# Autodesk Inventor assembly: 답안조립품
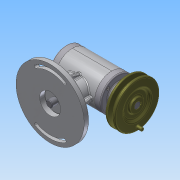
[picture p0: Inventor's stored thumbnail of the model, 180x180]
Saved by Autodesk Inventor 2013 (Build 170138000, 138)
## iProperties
Created: 2017-06
Part Number: 답안조립품
Document SubType Name: Assembly
Designer: Administrator
Mass: 1982.53 g
Surface Area: 1464.34 cm^2
Volume: 498.976 cm^3
Density: 3.97319 g/cm^3
Author: Administrator
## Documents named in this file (15)
- C:\Users\Administrator\Desktop\370608V1013\답안조립품.iam
- C:\Users\Administrator\Desktop\370608V1013\본체.ipt
- C:\Users\Administrator\Desktop\370608V1013\V-벨트풀리.ipt
- C:\Users\Administrator\Desktop\370608V1013\뒤커버.ipt
- C:\Users\Administrator\Desktop\370608V1013\멈춤나사 M3x8.ipt
- C:\Users\Administrator\Desktop\370608V1013\베어링 6201.ipt
- C:\Users\Administrator\Desktop\370608V1013\베어링 6202.ipt
- C:\Users\Administrator\Desktop\370608V1013\본체커버.ipt
- C:\Users\Administrator\Desktop\370608V1013\볼트 M3x0.5x8.ipt
- C:\Users\Administrator\Desktop\370608V1013\스프링 - [가변].ipt
- C:\Users\Administrator\Desktop\370608V1013\슬라이드.ipt
- C:\Users\Administrator\Desktop\370608V1013\앞커버.ipt
- C:\Users\Administrator\Desktop\370608V1013\오일실 12 22 7.ipt
- C:\Users\Administrator\Desktop\370608V1013\키 4 x 4 x 18.ipt
- C:\Users\Administrator\Desktop\370608V1013\편심축.ipt
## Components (1 placed, 1 different names)
1. V-벨트풀리:1
